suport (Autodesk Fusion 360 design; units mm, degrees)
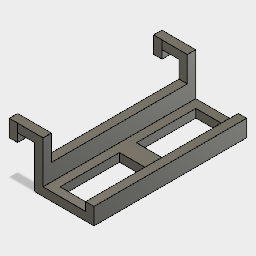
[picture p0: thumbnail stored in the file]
box_primitive "BoxPrimitive5" DistanceX 180 DistanceY 70 DistanceZ 90 OffsetDistanceX 0 OffsetDistanceY 0
shell "Shell1" innerThickness 10
box_primitive "BoxPrimitive6" DistanceX 160 DistanceY 60 DistanceZ -10 OffsetDistanceX 0 OffsetDistanceY 0
box_primitive "BoxPrimitive7" DistanceX 50 DistanceY 160 DistanceZ -10 OffsetDistanceX 0 OffsetDistanceY 0
box_primitive "BoxPrimitive8" DistanceX 10 DistanceY 160 DistanceZ -10 OffsetDistanceX 0 OffsetDistanceY 0
box_primitive "BoxPrimitive9" DistanceX 10 DistanceY 50 DistanceZ -10 OffsetDistanceX 0 OffsetDistanceY 0
box_primitive "BoxPrimitive10" DistanceX 60 DistanceY 60 DistanceZ -10 OffsetDistanceX 0 OffsetDistanceY 0
box_primitive "BoxPrimitive12" DistanceX 10 DistanceY 50 DistanceZ -10 OffsetDistanceX 0 OffsetDistanceY 0
box_primitive "BoxPrimitive13" DistanceX 10 DistanceY 50 DistanceZ 80 OffsetDistanceX 0 OffsetDistanceY 0
box_primitive "BoxPrimitive11" DistanceX 50 DistanceY 160 DistanceZ -10 OffsetDistanceX 0 OffsetDistanceY 0
box_primitive "BoxPrimitive14" DistanceX 10 DistanceY 10 DistanceZ 80 OffsetDistanceX 0 OffsetDistanceY 0
copy_paste_bodies "CopyPasteBodies1"
box_primitive "BoxPrimitive15" DistanceX 160 DistanceY 40 DistanceZ -10 OffsetDistanceX 0 OffsetDistanceY 0
box_primitive "BoxPrimitive16" DistanceX 20 DistanceY 160 DistanceZ -10 OffsetDistanceX 0 OffsetDistanceY 0
box_primitive "BoxPrimitive17" DistanceX 20 DistanceY 40 DistanceZ 10 OffsetDistanceX 0 OffsetDistanceY 0
box_primitive "BoxPrimitive18" DistanceX 10 DistanceY 20 DistanceZ -10 OffsetDistanceX 0 OffsetDistanceY 0
box_primitive "BoxPrimitive19" DistanceX 20 DistanceY 10 DistanceZ 10 OffsetDistanceX 0 OffsetDistanceY 0
move_face "MoveFace1"
move "Move4"
form "Form1"
box_primitive "BoxPrimitive20" DistanceX 180 DistanceY 10 DistanceZ -20 OffsetDistanceX 0 OffsetDistanceY 0
box_primitive "BoxPrimitive21" DistanceX 180 DistanceY 30 DistanceZ -30 OffsetDistanceX 0 OffsetDistanceY 0
box_primitive "BoxPrimitive22" DistanceX 180 DistanceY 10 DistanceZ 10 OffsetDistanceX 0 OffsetDistanceY 0
box_primitive "BoxPrimitive23" DistanceX 10 DistanceY 30 DistanceZ -10 OffsetDistanceX 0 OffsetDistanceY 0
copy_paste_bodies "CopyPasteBodies2"
move "Move5"
combine "Combine2"
combine "Combine3"
move "Move1"
move "Move2"
move "Move3"
combine "Combine1"
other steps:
base_feature "Base Feature1"
base_feature "Base Feature2"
